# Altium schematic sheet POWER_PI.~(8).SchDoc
size A; SheetNumber: 1; SheetTotal: 2
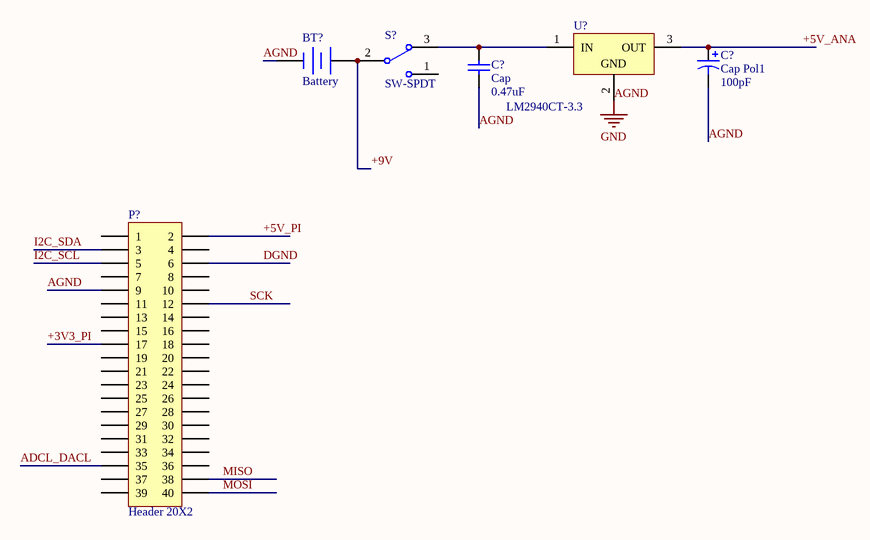
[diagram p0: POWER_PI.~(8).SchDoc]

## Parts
(Parts that share a designator on the sheet are numbered #1, #2 ... from top to bottom, then left to right.)
BT?  Battery  [BAT-2]
C?#1  Cap Pol1  value 100pF  [RB7.6-15]
C?#2  Cap  value 0.47uF  [RAD-0.3]
P?  Header 20X2  [HDR2X20]
S?  SW-SPDT  [SW DPST jameco]
U?  LM2940CT-3.3  [T03B]

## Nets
AGND: BT?.2(-) C?#1.2 C?#2.1 P?.9 U?.2(GND)  [also labelled GND]
+3V3_PI: P?.17
+5V_ANA: C?#1.1 U?.3(OUT)
+5V_PI: P?.2
+9V: BT?.1(+) S?.2
ADCL_DACL: P?.35
DGND: P?.6
I2C_SCL: P?.5
I2C_SDA: P?.3
MISO: P?.38
MOSI: P?.40
SCK: P?.12
NetC?#2_2: C?#2.2 S?.3 U?.1(IN)

Not connected (* = marked no-connect by the designer): P? 1 4 7 8 10 11 13 14 15 16 18 19 20 21 22 23 24 25 26 27 28 29 30 31 32 33 34 36 37 39; S? 1

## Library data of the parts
BT? = Battery: Multicell Battery
C?#1 = Cap Pol1: Polarized Capacitor (Radial)
C?#2 = Cap: Capacitor
P? = Header 20X2: Header, 20-Pin, Dual row
S? = SW-SPDT: SPDT Subminiature Toggle Switch, Right Angle Mounting, Vertical Actuation
U? = LM2940CT-5.0: 1A Low Dropout Regulator, 3-pin TO-220; Manufacturer: National Semiconductor; PackageTopMarking: NSUZXYTTE#*LM2940CT*-5.0 P+; PowerWise: N; CompType: LDO IC; High-Reliability: Y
